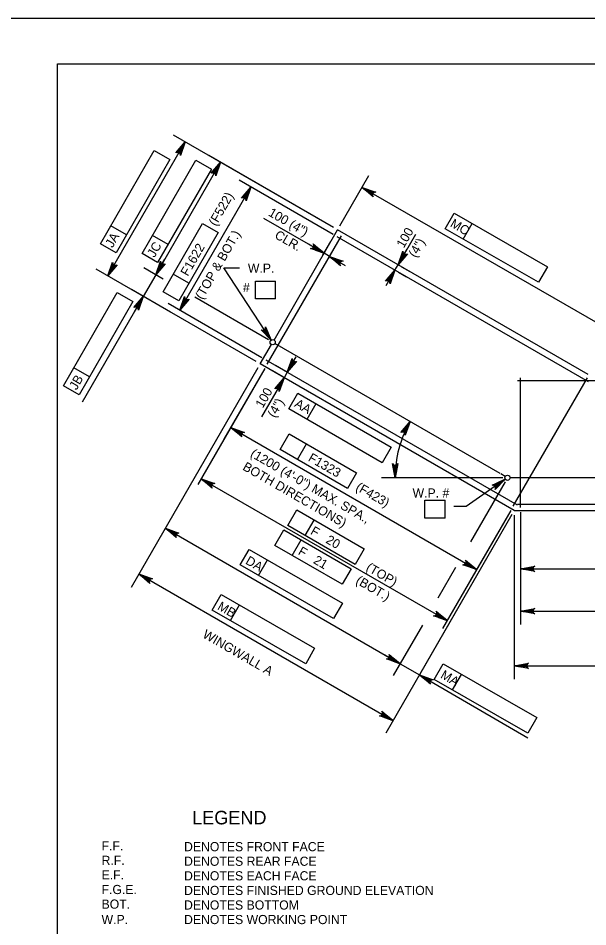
# Model space of a CAD drawing. Extents: x 634540 to 640306, y 296059 to 300275.
# Drawn here: x 639303.6 to 639490.3, y 298137.5 to 298435.5 of the extents above; entities that cross this region are included whole.
import ezdxf

# ---------------------------------------------------------------- set-up
doc = ezdxf.new("R2010")
doc.units = 0
for name, color, linetype in [('10', 7, 'Continuous'), ('2', 7, 'Continuous'), ('3', 7, 'Continuous'), ('4', 7, 'Continuous'), ('6', 7, 'Continuous'), ('PLT-BNDY', 7, 'Continuous')]:
    doc.layers.add(name, color=color, linetype=linetype)

msp = doc.modelspace()

# ---------------------------------------------------------------- linework, layer by layer
at = {"layer": '10'}
for p, q in [((639387.45, 298329.93), (639408.3, 298366.05)), ((639490.47, 298318.61), (639408.3, 298366.05)), ((639382.92, 298322.09), (639386.6, 298328.46)), ((639461.61, 298286.13), (639387.76, 298328.77)), ((639466.22, 298274), (639382.92, 298322.09)), ((639463.24, 298285.2), (639461.83, 298286.01)), ((639508.03, 298284.77), (639464.82, 298284.77)), ((639466.22, 298274), (639685.9, 298274))]:
    msp.add_line(p, q, dxfattribs=at)
at = {"layer": '2'}
for p, q in [((639316.46, 297856.46), (639316.46, 298420.46)), ((639316.46, 298420.46), (640102.46, 298420.46))]:
    msp.add_line(p, q, dxfattribs=at)
at = {"layer": '3'}
for points in [[(639369.94, 298388.2), (639368.36, 298383.72), (639368.33, 298384.16), (639368.15, 298384.48), (639367.9, 298384.68), (639367.61, 298384.79), (639367.24, 298384.78), (639366.85, 298384.6), (639369.94, 298388.2), (639367.24, 298384.78), (639367.61, 298384.79), (639369.94, 298388.2), (639367.9, 298384.68), (639368.15, 298384.48), (639369.94, 298388.2), (639368.33, 298384.16)], [(639332.97, 298350.93), (639334.55, 298355.41), (639334.57, 298355.19), (639334.58, 298354.97), (639334.67, 298354.81), (639334.76, 298354.65), (639334.88, 298354.55), (639335.01, 298354.45), (639335.15, 298354.4), (639335.3, 298354.34), (639335.48, 298354.34), (639335.67, 298354.34), (639335.86, 298354.44), (639336.06, 298354.53), (639332.97, 298350.93), (639335.86, 298354.44), (639335.67, 298354.34), (639332.97, 298350.93), (639335.48, 298354.34), (639335.3, 298354.34), (639332.97, 298350.93), (639335.15, 298354.4), (639335.01, 298354.45), (639332.97, 298350.93), (639334.88, 298354.55), (639334.76, 298354.65), (639332.97, 298350.93), (639334.67, 298354.81), (639334.58, 298354.97), (639332.97, 298350.93), (639334.57, 298355.19)], [(639453.88, 298254.68), (639449.4, 298256.25), (639449.62, 298256.27), (639449.84, 298256.29), (639450, 298256.38), (639450.16, 298256.47), (639450.26, 298256.59), (639450.36, 298256.71), (639450.41, 298256.86), (639450.47, 298257.01), (639450.47, 298257.19), (639450.46, 298257.37), (639450.37, 298257.57), (639450.28, 298257.77), (639453.88, 298254.68), (639450.37, 298257.57), (639450.46, 298257.37), (639453.88, 298254.68), (639450.47, 298257.19), (639450.47, 298257.01), (639453.88, 298254.68), (639450.41, 298256.86), (639450.36, 298256.71), (639453.88, 298254.68), (639450.26, 298256.59), (639450.16, 298256.47), (639453.88, 298254.68), (639450, 298256.38), (639449.84, 298256.29), (639453.88, 298254.68), (639449.62, 298256.27)]]:
    msp.add_lwpolyline(points, dxfattribs=at)
at = {"layer": '4'}
for p, q in [((639406.97, 298366.82), (639354.52, 298397.1)), ((639332.97, 298350.93), (639358.35, 298394.88)), ((639330.54, 298361.46), (639348.19, 298392.03)), ((639348.19, 298392.03), (639353.31, 298389.08)), ((639406.97, 298366.82), (639366.1, 298390.41)), ((639353.31, 298389.08), (639335.65, 298358.51)), ((639344.17, 298358.33), (639361.82, 298388.9)), ((639369.94, 298388.2), (639348.66, 298351.35)), ((639361.82, 298388.9), (639366.94, 298385.95)), ((639366.94, 298385.95), (639349.29, 298355.37)), ((639406.83, 298364.53), (639376.06, 298382.29)), ((639409.07, 298367.38), (639418.57, 298383.83)), ((639356.57, 298339.68), (639379.89, 298380.08)), ((639416.35, 298379.99), (639498.52, 298332.55)), ((639403.86, 298358.37), (639384.07, 298369.79)), ((639443.53, 298366.44), (639446.48, 298371.56)), ((639446.48, 298371.56), (639477.09, 298353.97)), ((639339.08, 298364.44), (639333.96, 298367.39)), ((639351.11, 298345.77), (639364, 298368.09)), ((639364, 298368.09), (639369.11, 298365.14)), ((639474.15, 298348.85), (639443.53, 298366.44)), ((639449.47, 298363.03), (639452.41, 298368.15)), ((639352.71, 298361.3), (639347.59, 298364.25)), ((639369.11, 298365.14), (639356.22, 298342.81)), ((639428.11, 298354.61), (639433.93, 298364.69)), ((639335.65, 298358.51), (639330.54, 298361.46)), ((639401.31, 298359.84), (639398.75, 298361.32)), ((639403.5, 298357.73), (639406.08, 298362.2)), ((639405.27, 298356.71), (639407.85, 298361.18)), ((639349.29, 298355.37), (639344.17, 298358.33)), ((639405.64, 298357.34), (639403.86, 298358.36)), ((639429.59, 298357.17), (639431.06, 298359.72)), ((639350.13, 298353.91), (639351.61, 298356.46)), ((639405.64, 298357.34), (639410.75, 298354.39)), ((639427.08, 298352.83), (639428.11, 298354.61)), ((639381.59, 298322.86), (639329.14, 298353.15)), ((639351.15, 298349.91), (639344.82, 298353.56)), ((639359.52, 298348.52), (639354.4, 298351.47)), ((639371, 298353.59), (639376.08, 298353.59)), ((639386.51, 298329.87), (639371, 298353.59)), ((639427.08, 298352.83), (639424.13, 298347.72)), ((639428.21, 298352.18), (639430.92, 298350.62)), ((639429.23, 298353.96), (639431.94, 298352.39)), ((639477.09, 298353.97), (639474.15, 298348.85)), ((639348.66, 298351.35), (639344.56, 298344.24)), ((639381.39, 298349.28), (639387.98, 298349.28)), ((639381.39, 298343.38), (639381.39, 298349.28)), ((639387.98, 298343.38), (639387.98, 298349.28)), ((639353.52, 298339.07), (639340.72, 298346.46)), ((639356.22, 298342.81), (639351.11, 298345.77)), ((639318.42, 298314.89), (639336.07, 298345.46)), ((639344.56, 298344.24), (639324.55, 298309.59)), ((639336.07, 298345.46), (639341.19, 298342.51)), ((639385.69, 298329.97), (639361.47, 298343.95)), ((639387.98, 298343.38), (639381.39, 298343.38)), ((639341.19, 298342.51), (639323.54, 298311.94)), ((639343.08, 298341.69), (639341.61, 298339.13)), ((639383.5, 298324.13), (639352.73, 298341.89)), ((639391.79, 298319.34), (639394.74, 298324.46)), ((639326.96, 298317.86), (639321.85, 298320.82)), ((639382.15, 298320.76), (639340.63, 298248.84)), ((639384.44, 298320.62), (639362.45, 298282.54)), ((639384.44, 298320.62), (639371.03, 298297.4)), ((639390.33, 298317.82), (639386.93, 298319.78)), ((639391.36, 298319.59), (639387.95, 298321.56)), ((639391.79, 298319.34), (639390.77, 298317.57)), ((639390.76, 298317.57), (639383.35, 298304.72)), ((639323.54, 298311.94), (639318.42, 298314.89)), ((639389.29, 298315.01), (639387.81, 298312.45)), ((639392.35, 298307.39), (639395.31, 298312.5)), ((639395.31, 298312.5), (639425.86, 298294.82)), ((639422.91, 298289.71), (639392.35, 298307.39)), ((639398.27, 298303.96), (639401.23, 298309.07)), ((639373.25, 298301.23), (639453.88, 298254.68)), ((639389.46, 298294.02), (639392.41, 298299.13)), ((639392.41, 298299.13), (639414.53, 298286.36)), ((639395.17, 298290.72), (639398.12, 298295.84)), ((639411.57, 298281.25), (639389.46, 298294.02)), ((639425.86, 298294.82), (639422.91, 298289.71)), ((639414.53, 298286.36), (639411.57, 298281.25)), ((639363.57, 298284.47), (639444.2, 298237.92)), ((639462.44, 298284.77), (639422.71, 298284.77)), ((639463.25, 298284.32), (639450.4, 298275.38)), ((639463.21, 298283.44), (639451.86, 298263.78)), ((639436.93, 298277.47), (639443.52, 298277.47)), ((639436.93, 298271.56), (639436.93, 298277.47)), ((639443.52, 298271.56), (639443.52, 298277.47)), ((639391.93, 298269.09), (639394.89, 298274.2)), ((639394.89, 298274.2), (639417, 298261.43)), ((639465.07, 298274.07), (639442.72, 298235.36)), ((639450.4, 298275.38), (639446.36, 298275.38)), ((639465.07, 298274.07), (639451.66, 298250.84)), ((639465.45, 298272.67), (639424.07, 298201)), ((639465.45, 298272.67), (639435.11, 298220.13)), ((639443.52, 298271.56), (639436.93, 298271.56)), ((639466.22, 298272.47), (639466.22, 298218.7)), ((639468.27, 298273.49), (639468.27, 298236.63)), ((639468.27, 298273.49), (639468.27, 298250.51)), ((639351.82, 298268.21), (639428.77, 298223.79)), ((639414.05, 298256.32), (639391.93, 298269.09)), ((639397.64, 298265.79), (639400.6, 298270.9)), ((639387.67, 298262.61), (639390.62, 298267.72)), ((639390.62, 298267.72), (639412.74, 298254.95)), ((639409.79, 298249.84), (639387.67, 298262.61)), ((639393.38, 298259.31), (639396.33, 298264.43)), ((639376.39, 298256.17), (639379.33, 298261.29)), ((639379.33, 298261.29), (639409.94, 298243.7)), ((639417, 298261.43), (639414.05, 298256.32)), ((639407, 298238.58), (639376.39, 298256.17)), ((639382.32, 298252.75), (639385.27, 298257.88)), ((639343.16, 298253.22), (639426.45, 298205.13)), ((639412.74, 298254.95), (639409.79, 298249.84)), ((639446.97, 298255.31), (639441.18, 298245.28)), ((639468.27, 298254.94), (639683.85, 298254.94)), ((639367.21, 298241.38), (639370.16, 298246.5)), ((639370.16, 298246.5), (639400.77, 298228.91)), ((639397.83, 298223.79), (639367.21, 298241.38)), ((639373.15, 298237.97), (639376.09, 298243.09)), ((639409.94, 298243.7), (639407, 298238.58)), ((639468.27, 298241.06), (639683.85, 298241.06)), ((639436.09, 298236.47), (639426.55, 298219.95)), ((639400.77, 298228.91), (639397.83, 298223.79)), ((639426.21, 298225.26), (639423.65, 298226.74)), ((639428.77, 298223.79), (639435.11, 298220.13)), ((639440, 298218.6), (639442.95, 298223.72)), ((639442.95, 298223.72), (639473.56, 298206.14)), ((639466.22, 298223.13), (639685.9, 298223.13)), ((639435.12, 298220.14), (639470.69, 298199.5)), ((639437.67, 298218.65), (639440.22, 298217.17)), ((639470.62, 298201.02), (639440, 298218.6)), ((639445.94, 298215.19), (639448.88, 298220.31)), ((639473.56, 298206.14), (639470.62, 298201.02))]:
    msp.add_line(p, q, dxfattribs=at)
for points in [[(639358.35, 298394.88), (639356.78, 298390.41), (639356.74, 298390.85), (639356.56, 298391.16), (639356.32, 298391.37), (639356.02, 298391.48), (639355.66, 298391.47), (639355.26, 298391.28), (639358.35, 298394.88), (639355.66, 298391.47), (639356.02, 298391.48), (639358.35, 298394.88), (639356.32, 298391.37), (639356.56, 298391.16), (639358.35, 298394.88), (639356.74, 298390.85)], [(639379.89, 298380.08), (639378.32, 298375.61), (639378.28, 298376.04), (639378.1, 298376.36), (639377.86, 298376.56), (639377.56, 298376.67), (639377.2, 298376.67), (639376.8, 298376.48), (639379.89, 298380.08), (639377.2, 298376.67), (639377.56, 298376.67), (639379.89, 298380.08), (639377.86, 298376.56), (639378.1, 298376.36), (639379.89, 298380.08), (639378.28, 298376.04)], [(639416.35, 298379.99), (639420.83, 298378.42), (639420.39, 298378.39), (639420.07, 298378.21), (639419.87, 298377.96), (639419.76, 298377.66), (639419.76, 298377.3), (639419.95, 298376.91), (639416.35, 298379.99), (639419.76, 298377.3), (639419.76, 298377.66), (639416.35, 298379.99), (639419.87, 298377.96), (639420.07, 298378.21), (639416.35, 298379.99), (639420.39, 298378.39)], [(639403.86, 298358.37), (639399.39, 298359.94), (639399.83, 298359.98), (639400.14, 298360.16), (639400.35, 298360.4), (639400.46, 298360.69), (639400.45, 298361.06), (639400.27, 298361.45), (639403.86, 298358.37), (639400.45, 298361.06), (639400.46, 298360.69), (639403.86, 298358.37), (639400.35, 298360.4), (639400.14, 298360.16), (639403.86, 298358.37), (639399.83, 298359.98)], [(639428.11, 298354.61), (639429.68, 298359.08), (639429.72, 298358.65), (639429.9, 298358.33), (639430.14, 298358.13), (639430.44, 298358.02), (639430.8, 298358.02), (639431.2, 298358.21), (639428.11, 298354.61), (639430.8, 298358.02), (639430.44, 298358.02), (639428.11, 298354.61), (639430.14, 298358.13), (639429.9, 298358.33), (639428.11, 298354.61), (639429.72, 298358.65)], [(639348.66, 298351.35), (639350.23, 298355.82), (639350.27, 298355.39), (639350.45, 298355.07), (639350.69, 298354.87), (639350.99, 298354.76), (639351.35, 298354.76), (639351.75, 298354.95), (639348.66, 298351.35), (639351.35, 298354.76), (639350.99, 298354.76), (639348.66, 298351.35), (639350.69, 298354.87), (639350.45, 298355.07), (639348.66, 298351.35), (639350.27, 298355.39)], [(639405.64, 298357.34), (639410.11, 298355.76), (639409.68, 298355.73), (639409.36, 298355.55), (639409.16, 298355.31), (639409.05, 298355.01), (639409.05, 298354.64), (639409.24, 298354.25), (639405.64, 298357.34), (639409.05, 298354.64), (639409.05, 298355.01), (639405.64, 298357.34), (639409.16, 298355.31), (639409.36, 298355.55), (639405.64, 298357.34), (639409.68, 298355.73)], [(639427.08, 298352.83), (639425.51, 298348.36), (639425.47, 298348.8), (639425.3, 298349.11), (639425.05, 298349.32), (639424.75, 298349.42), (639424.39, 298349.42), (639424, 298349.23), (639427.08, 298352.83), (639424.39, 298349.42), (639424.75, 298349.42), (639427.08, 298352.83), (639425.05, 298349.32), (639425.3, 298349.11), (639427.08, 298352.83), (639425.47, 298348.8)], [(639344.56, 298344.24), (639342.98, 298339.77), (639342.95, 298340.21), (639342.77, 298340.52), (639342.53, 298340.73), (639342.23, 298340.84), (639341.87, 298340.83), (639341.47, 298340.64), (639344.56, 298344.24), (639341.87, 298340.83), (639342.23, 298340.84), (639344.56, 298344.24), (639342.53, 298340.73), (639342.77, 298340.52), (639344.56, 298344.24), (639342.95, 298340.21)], [(639356.57, 298339.68), (639358.14, 298344.15), (639358.17, 298343.71), (639358.35, 298343.4), (639358.6, 298343.2), (639358.9, 298343.09), (639359.26, 298343.09), (639359.65, 298343.28), (639356.57, 298339.68), (639359.26, 298343.09), (639358.9, 298343.09), (639356.57, 298339.68), (639358.6, 298343.2), (639358.35, 298343.4), (639356.57, 298339.68), (639358.17, 298343.71)], [(639386.51, 298329.87), (639383.23, 298333.3), (639383.63, 298333.13), (639383.99, 298333.15), (639384.28, 298333.27), (639384.52, 298333.49), (639384.68, 298333.81), (639384.69, 298334.25), (639386.51, 298329.87), (639384.68, 298333.81), (639384.52, 298333.49), (639386.51, 298329.87), (639384.28, 298333.27), (639383.99, 298333.15), (639386.51, 298329.87), (639383.63, 298333.13)], [(639391.79, 298319.34), (639393.36, 298323.82), (639393.4, 298323.38), (639393.58, 298323.06), (639393.82, 298322.86), (639394.12, 298322.75), (639394.48, 298322.76), (639394.88, 298322.94), (639391.79, 298319.34), (639394.48, 298322.76), (639394.12, 298322.75), (639391.79, 298319.34), (639393.82, 298322.86), (639393.58, 298323.06), (639391.79, 298319.34), (639393.4, 298323.38)], [(639390.76, 298317.57), (639389.19, 298313.09), (639389.16, 298313.53), (639388.98, 298313.84), (639388.73, 298314.05), (639388.43, 298314.16), (639388.07, 298314.15), (639387.68, 298313.97), (639390.76, 298317.57), (639388.07, 298314.15), (639388.43, 298314.16), (639390.76, 298317.57), (639388.73, 298314.05), (639388.98, 298313.84), (639390.76, 298317.57), (639389.16, 298313.53)], [(639373.25, 298301.23), (639377.72, 298299.66), (639377.28, 298299.62), (639376.97, 298299.44), (639376.77, 298299.2), (639376.65, 298298.9), (639376.66, 298298.54), (639376.85, 298298.14), (639373.25, 298301.23), (639376.66, 298298.54), (639376.65, 298298.9), (639373.25, 298301.23), (639376.77, 298299.2), (639376.97, 298299.44), (639373.25, 298301.23), (639377.28, 298299.62)], [(639432.07, 298303.19), (639430.5, 298298.72), (639430.46, 298299.15), (639430.28, 298299.47), (639430.04, 298299.67), (639429.74, 298299.78), (639429.38, 298299.78), (639428.98, 298299.59), (639432.07, 298303.19), (639429.38, 298299.78), (639429.74, 298299.78), (639432.07, 298303.19), (639430.04, 298299.67), (639430.28, 298299.47), (639432.07, 298303.19), (639430.46, 298299.15)], [(639427.14, 298284.77), (639426.26, 298289.43), (639426.51, 298289.07), (639426.82, 298288.89), (639427.14, 298288.83), (639427.45, 298288.89), (639427.76, 298289.07), (639428.01, 298289.43), (639427.14, 298284.77), (639427.76, 298289.07), (639427.45, 298288.89), (639427.14, 298284.77), (639427.14, 298288.83), (639426.82, 298288.89), (639427.14, 298284.77), (639426.51, 298289.07)], [(639363.57, 298284.47), (639368.04, 298282.9), (639367.61, 298282.86), (639367.29, 298282.68), (639367.09, 298282.44), (639366.98, 298282.14), (639366.98, 298281.78), (639367.17, 298281.38), (639363.57, 298284.47), (639366.98, 298281.78), (639366.98, 298282.14), (639363.57, 298284.47), (639367.09, 298282.44), (639367.29, 298282.68), (639363.57, 298284.47), (639367.61, 298282.86)], [(639463.25, 298284.32), (639459.93, 298280.94), (639460.08, 298281.35), (639460.05, 298281.72), (639459.92, 298282), (639459.69, 298282.23), (639459.36, 298282.38), (639458.93, 298282.38), (639463.25, 298284.32), (639459.36, 298282.38), (639459.69, 298282.23), (639463.25, 298284.32), (639459.92, 298282), (639460.05, 298281.72), (639463.25, 298284.32), (639460.08, 298281.35)], [(639351.82, 298268.21), (639356.29, 298266.64), (639355.85, 298266.61), (639355.54, 298266.43), (639355.33, 298266.18), (639355.22, 298265.88), (639355.23, 298265.52), (639355.42, 298265.13), (639351.82, 298268.21), (639355.23, 298265.52), (639355.22, 298265.88), (639351.82, 298268.21), (639355.33, 298266.18), (639355.54, 298266.43), (639351.82, 298268.21), (639355.85, 298266.61)], [(639343.16, 298253.22), (639347.63, 298251.65), (639347.2, 298251.61), (639346.88, 298251.44), (639346.68, 298251.19), (639346.57, 298250.89), (639346.57, 298250.53), (639346.76, 298250.14), (639343.16, 298253.22), (639346.57, 298250.53), (639346.57, 298250.89), (639343.16, 298253.22), (639346.68, 298251.19), (639346.88, 298251.44), (639343.16, 298253.22), (639347.2, 298251.61)], [(639468.27, 298254.94), (639472.93, 298255.81), (639472.57, 298255.56), (639472.38, 298255.25), (639472.33, 298254.94), (639472.38, 298254.62), (639472.57, 298254.31), (639472.93, 298254.06), (639468.27, 298254.94), (639472.57, 298254.31), (639472.38, 298254.62), (639468.27, 298254.94), (639472.33, 298254.94), (639472.38, 298255.25), (639468.27, 298254.94), (639472.57, 298255.56)], [(639468.27, 298241.06), (639472.93, 298241.94), (639472.57, 298241.69), (639472.38, 298241.37), (639472.33, 298241.06), (639472.38, 298240.75), (639472.57, 298240.44), (639472.93, 298240.19), (639468.27, 298241.06), (639472.57, 298240.44), (639472.38, 298240.75), (639468.27, 298241.06), (639472.33, 298241.06), (639472.38, 298241.37), (639468.27, 298241.06), (639472.57, 298241.69)], [(639444.2, 298237.92), (639439.72, 298239.49), (639440.16, 298239.53), (639440.48, 298239.7), (639440.68, 298239.95), (639440.79, 298240.25), (639440.78, 298240.61), (639440.6, 298241), (639444.2, 298237.92), (639440.78, 298240.61), (639440.79, 298240.25), (639444.2, 298237.92), (639440.68, 298239.95), (639440.48, 298239.7), (639444.2, 298237.92), (639440.16, 298239.53)], [(639428.77, 298223.79), (639424.29, 298225.36), (639424.73, 298225.39), (639425.04, 298225.57), (639425.25, 298225.82), (639425.36, 298226.12), (639425.35, 298226.48), (639425.17, 298226.87), (639428.77, 298223.79), (639425.35, 298226.48), (639425.36, 298226.12), (639428.77, 298223.79), (639425.25, 298225.82), (639425.04, 298225.57), (639428.77, 298223.79), (639424.73, 298225.39)], [(639466.22, 298223.13), (639470.88, 298224), (639470.52, 298223.75), (639470.33, 298223.44), (639470.28, 298223.13), (639470.33, 298222.81), (639470.52, 298222.5), (639470.88, 298222.25), (639466.22, 298223.13), (639470.52, 298222.5), (639470.33, 298222.81), (639466.22, 298223.13), (639470.28, 298223.13), (639470.33, 298223.44), (639466.22, 298223.13), (639470.52, 298223.75)], [(639435.12, 298220.14), (639439.59, 298218.55), (639439.15, 298218.52), (639438.83, 298218.34), (639438.63, 298218.1), (639438.52, 298217.8), (639438.52, 298217.44), (639438.71, 298217.04), (639435.12, 298220.14), (639438.52, 298217.44), (639438.52, 298217.8), (639435.12, 298220.14), (639438.63, 298218.1), (639438.83, 298218.34), (639435.12, 298220.14), (639439.15, 298218.52)], [(639426.45, 298205.13), (639421.98, 298206.71), (639422.42, 298206.74), (639422.73, 298206.92), (639422.94, 298207.16), (639423.05, 298207.46), (639423.04, 298207.83), (639422.85, 298208.22), (639426.45, 298205.13), (639423.04, 298207.83), (639423.05, 298207.46), (639426.45, 298205.13), (639422.94, 298207.16), (639422.73, 298206.92), (639426.45, 298205.13), (639422.42, 298206.74)]]:
    msp.add_lwpolyline(points, dxfattribs=at)
for points in [[(639356.45, 298392.57), (639357.3, 298392.08), (639358.35, 298394.88)], [(639368.03, 298385.89), (639368.88, 298385.39), (639369.93, 298388.2)], [(639377.99, 298377.77), (639378.84, 298377.28), (639379.89, 298380.08)], [(639419.15, 298378.94), (639418.66, 298378.09), (639416.35, 298379.99)], [(639401.55, 298360.27), (639401.06, 298359.42), (639403.86, 298358.36)], [(639429.16, 298357.41), (639430.01, 298356.92), (639428.11, 298354.61)], [(639408.44, 298356.29), (639407.95, 298355.44), (639405.64, 298357.34)], [(639349.71, 298354.15), (639350.56, 298353.66), (639348.66, 298351.35)], [(639425.18, 298350.52), (639426.03, 298350.03), (639427.08, 298352.83)], [(639342.66, 298341.93), (639343.51, 298341.44), (639344.56, 298344.24)], [(639357.62, 298342.48), (639358.47, 298341.99), (639356.57, 298339.68)], [(639385.3, 298332.61), (639384.48, 298332.07), (639386.51, 298329.87)], [(639392.84, 298322.15), (639393.69, 298321.65), (639391.79, 298319.34)], [(639388.86, 298315.26), (639389.72, 298314.76), (639390.77, 298317.57)], [(639376.05, 298300.18), (639375.56, 298299.33), (639373.25, 298301.23)], [(639430.26, 298300.8), (639431.13, 298300.35), (639432.07, 298303.19)], [(639426.76, 298287.74), (639427.75, 298287.7), (639427.14, 298284.77)], [(639366.37, 298283.42), (639365.88, 298282.57), (639363.57, 298284.47)], [(639460.55, 298283.04), (639461.11, 298282.23), (639463.25, 298284.32)], [(639354.62, 298267.17), (639354.13, 298266.31), (639351.82, 298268.22)], [(639345.96, 298252.17), (639345.47, 298251.32), (639343.16, 298253.22)], [(639471.22, 298255.43), (639471.22, 298254.44), (639468.27, 298254.94)], [(639471.22, 298241.55), (639471.22, 298240.57), (639468.27, 298241.06)], [(639441.89, 298239.82), (639441.4, 298238.97), (639444.2, 298237.92)], [(639426.45, 298225.69), (639425.96, 298224.84), (639428.77, 298223.79)], [(639469.17, 298223.62), (639469.17, 298222.63), (639466.22, 298223.13)], [(639437.91, 298219.08), (639437.42, 298218.22), (639435.11, 298220.13)], [(639424.14, 298207.04), (639423.65, 298206.18), (639426.45, 298205.13)]]:
    msp.add_lwpolyline(points, close=True, dxfattribs=at)
for centre in [(639387.02, 298329.2), (639463.97, 298284.77)]:
    msp.add_circle(centre, 0.85, dxfattribs=at)
msp.add_arc((639463.97, 298284.77), 36.84, 150, 180, dxfattribs=at)
at = {"layer": '6'}
for p, q in [((639385.21, 298321.96), (639409.56, 298364.13)), ((639490.57, 298316.18), (639408.16, 298363.76)), ((639467.24, 298275.78), (639384.84, 298323.36)), ((639465.84, 298275.41), (639490.19, 298317.58)), ((639523.8, 298316.55), (639467.24, 298316.55)), ((639468.27, 298275.03), (639468.27, 298317.58)), ((639467.24, 298276.06), (639684.87, 298276.06))]:
    msp.add_line(p, q, dxfattribs=at)
at = {"layer": 'PLT-BNDY'}
msp.add_lwpolyline([(639276.46, 298435.46), (640117.46, 298435.46), (640117.46, 297841.46), (639276.46, 297841.46)], close=True, dxfattribs=at)

# ---------------------------------------------------------------- texts
at = {"layer": '4'}
for s, height, rotation, p in [('(F522)', 3, 60, (639368.41, 298367.06)), ('100 (4")', 3, 330, (639385.34, 298370.87)), ('MC', 3, 330.127, (639444.96, 298367.26)), ('100', 3, 60, (639429.99, 298359.86)), ('JA', 3, 60, (639334.51, 298359.97)), ('(TOP & BOT.)', 3.0001, 60, (639364.01, 298342.98)), ('CLR.', 3, 330, (639387.41, 298363.51)), ('JC', 3, 60, (639348.27, 298356.76)), ('F1622', 3, 60, (639359.19, 298350.63)), ('(4")', 3, 60, (639433.95, 298356.72)), ('JB', 3, 60, (639322.7, 298313.32)), ('100', 3, 60, (639383.75, 298307.37)), ('(4")', 3, 60, (639387.71, 298304.23)), ('AA', 3, 329.9509, (639393.9, 298308.24)), ('(1200 (4\'-0") MAX. SPA.,', 3.0001, 330, (639379.42, 298291.87)), ('F1323', 3, 330, (639398.39, 298290.45)), ('BOTH DIRECTIONS)', 3.0001, 330, (639376.92, 298287.54)), ('(F423)', 3, 330, (639413.97, 298280.88)), ('F   20', 3, 330, (639399.16, 298266.47)), ('F   21', 3, 330, (639395.09, 298259.8)), ('DA', 3, 330.127, (639377.85, 298256.71)), ('(TOP)', 3, 330, (639417.34, 298254.53)), ('(BOT.)', 3, 330, (639413.99, 298250.28)), ('MB', 3, 330.127, (639368.66, 298241.75)), ('WINGWALL A', 3, 330, (639363.78, 298232.57)), ('MA', 3, 330.127, (639441.79, 298219.3))]:
    msp.add_text(s, height=height, rotation=rotation, dxfattribs=at).set_placement(p)
for s, height, p in [('W.P. ', 3, (639378.88, 298351.99)), ('#', 3, (639377.27, 298345.67)), ('W.P. #', 3, (639432.87, 298278.28)), ('LEGEND', 4.429, (639360.62, 298171.13)), ('F.F.', 3, (639330.91, 298162.61)), ('DENOTES FRONT FACE', 3.0001, (639357.95, 298162.32)), ('R.F.', 3, (639330.91, 298157.83)), ('DENOTES REAR FACE', 3.0001, (639357.95, 298157.54)), ('E.F.', 3, (639330.91, 298153.05)), ('DENOTES EACH FACE', 3.0001, (639357.95, 298152.76)), ('F.G.E.', 3, (639330.91, 298148.27)), ('DENOTES FINISHED GROUND ELEVATION', 3.0001, (639357.95, 298147.97)), ('BOT.', 3, (639330.91, 298143.48)), ('DENOTES BOTTOM', 3.0001, (639357.95, 298143.19)), ('W.P.', 3, (639330.91, 298138.42)), ('DENOTES WORKING POINT', 3.0001, (639357.95, 298138.42))]:
    msp.add_text(s, height=height, dxfattribs=at).set_placement(p)

doc.saveas('drawing.dxf')
